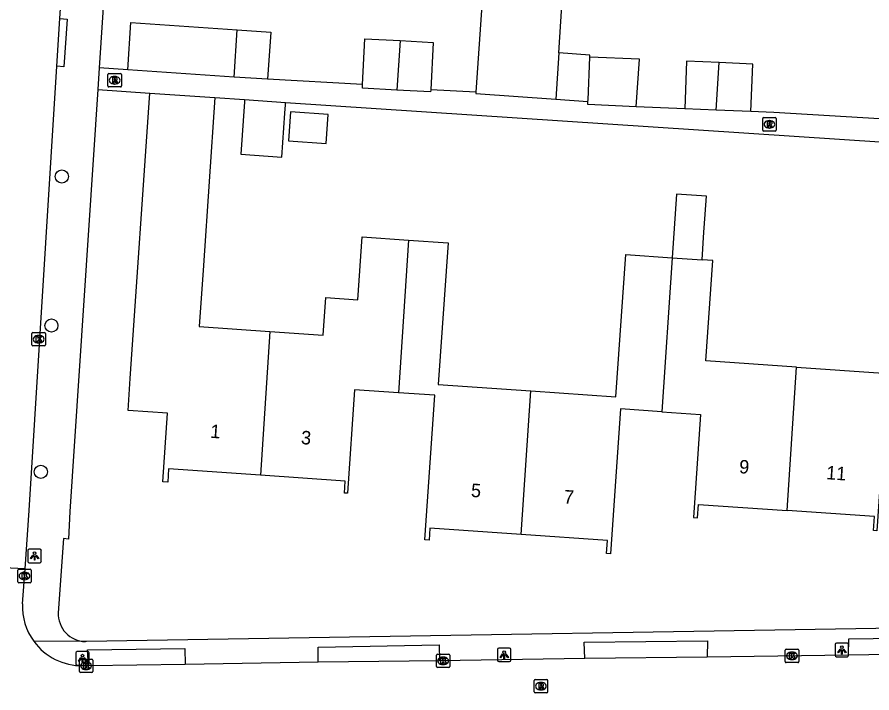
# Model space of a CAD drawing. Extents: x 161848 to 162726, y 385382 to 386521.
# Drawn here: x 162058.5 to 162122, y 385384.8 to 385435 of the extents above; entities that cross this region are included whole.
import ezdxf

# ---------------------------------------------------------------- set-up
doc = ezdxf.new("R2010")
doc.units = 0
for name, color, linetype in [('IMGEO_Boom', 7, 'Continuous'), ('IMGEO_Kolk', 7, 'Continuous'), ('IMGEO_Lichtpunt', 7, 'Continuous'), ('IMGEO_Pand', 7, 'Continuous'), ('IMGEO_Pand_nummerreeks', 7, 'Continuous'), ('IMGEO_Rijbaan_lokaal_open', 7, 'Continuous'), ('IMGEO_Rioolput', 7, 'Continuous'), ('IMGEO_Voetpad_open', 7, 'Continuous')]:
    doc.layers.add(name, color=color, linetype=linetype)

msp = doc.modelspace()

# ---------------------------------------------------------------- linework, layer by layer
at = {"layer": 'IMGEO_Boom'}
for centre in [(162061.81, 385423.185), (162061.04, 385412.111), (162060.257, 385401.24)]:
    msp.add_circle(centre, 0.489, dxfattribs=at)
at = {"layer": 'IMGEO_Kolk'}
for p, q in [((162059.594, 385410.674), (162059.594, 385411.526)), ((162059.669, 385411.6), (162060.521, 385411.6)), ((162060.082, 385411.38), (162060.107, 385411.38)), ((162060.595, 385411.526), (162060.595, 385410.674)), ((162060.521, 385410.6), (162059.669, 385410.6)), ((162060.105, 385410.82), (162060.08, 385410.82)), ((162058.54, 385393.081), (162058.54, 385393.933)), ((162058.615, 385394.007), (162059.467, 385394.007)), ((162059.028, 385393.787), (162059.053, 385393.787)), ((162059.541, 385393.933), (162059.541, 385393.081)), ((162059.467, 385393.007), (162058.615, 385393.007)), ((162059.051, 385393.227), (162059.026, 385393.227)), ((162089.736, 385387.698), (162090.588, 385387.698)), ((162115.596, 385387.142), (162115.596, 385387.994)), ((162115.671, 385388.068), (162116.523, 385388.068)), ((162116.084, 385387.848), (162116.109, 385387.848)), ((162116.597, 385387.994), (162116.597, 385387.142)), ((162063.118, 385386.406), (162063.118, 385387.258)), ((162063.193, 385387.332), (162064.045, 385387.332)), ((162063.606, 385387.112), (162063.631, 385387.112)), ((162064.119, 385387.258), (162064.119, 385386.406)), ((162089.661, 385386.772), (162089.661, 385387.624)), ((162090.149, 385387.478), (162090.174, 385387.478)), ((162090.662, 385387.624), (162090.662, 385386.772)), ((162116.523, 385387.068), (162115.671, 385387.068)), ((162116.107, 385387.288), (162116.082, 385387.288)), ((162063.629, 385386.552), (162063.604, 385386.552)), ((162090.588, 385386.698), (162089.736, 385386.698)), ((162090.172, 385386.918), (162090.147, 385386.918)), ((162064.045, 385386.332), (162063.193, 385386.332))]:
    msp.add_line(p, q, dxfattribs=at)
for points in [[(162059.594, 385410.674), (162059.594, 385411.526)], [(162059.669, 385411.6), (162060.521, 385411.6)], [(162059.915, 385411.3), (162060.038, 385411.3), (162060.038, 385411.149), (162060.168, 385411.3), (162060.332, 385411.3), (162060.186, 385411.149), (162060.339, 385410.9), (162060.187, 385410.9), (162060.102, 385411.064), (162060.038, 385410.997), (162060.038, 385410.9), (162059.915, 385410.9), (162059.915, 385411.3)], [(162060.595, 385411.526), (162060.595, 385410.674)], [(162060.521, 385410.6), (162059.669, 385410.6)], [(162058.54, 385393.081), (162058.54, 385393.933)], [(162058.615, 385394.007), (162059.467, 385394.007)], [(162058.861, 385393.707), (162058.984, 385393.707), (162058.984, 385393.556), (162059.114, 385393.707), (162059.278, 385393.707), (162059.132, 385393.556), (162059.285, 385393.307), (162059.133, 385393.307), (162059.048, 385393.471), (162058.984, 385393.404), (162058.984, 385393.307), (162058.861, 385393.307), (162058.861, 385393.707)], [(162059.541, 385393.933), (162059.541, 385393.081)], [(162059.467, 385393.007), (162058.615, 385393.007)], [(162089.736, 385387.698), (162090.588, 385387.698)], [(162115.596, 385387.142), (162115.596, 385387.994)], [(162115.671, 385388.068), (162116.523, 385388.068)], [(162115.917, 385387.768), (162116.04, 385387.768), (162116.04, 385387.617), (162116.17, 385387.768), (162116.334, 385387.768), (162116.188, 385387.617), (162116.341, 385387.368), (162116.189, 385387.368), (162116.104, 385387.532), (162116.04, 385387.465), (162116.04, 385387.368), (162115.917, 385387.368), (162115.917, 385387.768)], [(162116.597, 385387.994), (162116.597, 385387.142)], [(162063.118, 385386.406), (162063.118, 385387.258)], [(162063.193, 385387.332), (162064.045, 385387.332)], [(162064.119, 385387.258), (162064.119, 385386.406)], [(162089.661, 385386.772), (162089.661, 385387.624)], [(162089.982, 385387.398), (162090.105, 385387.398), (162090.105, 385387.247), (162090.235, 385387.398), (162090.399, 385387.398), (162090.253, 385387.247), (162090.406, 385386.998), (162090.254, 385386.998), (162090.169, 385387.162), (162090.105, 385387.095), (162090.105, 385386.998), (162089.982, 385386.998), (162089.982, 385387.398)], [(162090.662, 385387.624), (162090.662, 385386.772)], [(162116.523, 385387.068), (162115.671, 385387.068)], [(162063.439, 385387.032), (162063.562, 385387.032), (162063.562, 385386.881), (162063.692, 385387.032), (162063.856, 385387.032), (162063.71, 385386.881), (162063.863, 385386.632), (162063.711, 385386.632), (162063.626, 385386.796), (162063.562, 385386.729), (162063.562, 385386.632), (162063.439, 385386.632), (162063.439, 385387.032)], [(162090.588, 385386.698), (162089.736, 385386.698)], [(162064.045, 385386.332), (162063.193, 385386.332)]]:
    msp.add_lwpolyline(points, dxfattribs=at)
for centre, start, end in [((162059.671, 385411.524), 91.55205, 178.44795), ((162059.671, 385411.524), 91.55205, 178.44795), ((162060.519, 385411.524), 1.55205, 88.44795), ((162060.519, 385411.524), 1.55205, 88.44795), ((162059.671, 385410.676), 181.55205, 268.44795), ((162059.671, 385410.676), 181.55205, 268.44795), ((162060.519, 385410.676), 271.55205, 358.44795), ((162060.519, 385410.676), 271.55205, 358.44795), ((162058.617, 385393.931), 91.55205, 178.44795), ((162058.617, 385393.931), 91.55205, 178.44795), ((162059.465, 385393.931), 1.55205, 88.44795), ((162059.465, 385393.931), 1.55205, 88.44795), ((162058.617, 385393.083), 181.55205, 268.44795), ((162058.617, 385393.083), 181.55205, 268.44795), ((162059.465, 385393.083), 271.55205, 358.44795), ((162059.465, 385393.083), 271.55205, 358.44795), ((162089.738, 385387.622), 91.55205, 178.44795), ((162089.738, 385387.622), 91.55205, 178.44795), ((162090.586, 385387.622), 1.55205, 88.44795), ((162090.586, 385387.622), 1.55205, 88.44795), ((162115.673, 385387.992), 91.55205, 178.44795), ((162115.673, 385387.992), 91.55205, 178.44795), ((162116.521, 385387.992), 1.55205, 88.44795), ((162116.521, 385387.992), 1.55205, 88.44795), ((162063.195, 385387.256), 91.55205, 178.44795), ((162063.195, 385387.256), 91.55205, 178.44795), ((162064.043, 385387.256), 1.55205, 88.44795), ((162064.043, 385387.256), 1.55205, 88.44795), ((162115.673, 385387.144), 181.55205, 268.44795), ((162115.673, 385387.144), 181.55205, 268.44795), ((162116.521, 385387.144), 271.55205, 358.44795), ((162116.521, 385387.144), 271.55205, 358.44795), ((162063.195, 385386.408), 181.55205, 268.44795), ((162063.195, 385386.408), 181.55205, 268.44795), ((162064.043, 385386.408), 271.55205, 358.44795), ((162064.043, 385386.408), 271.55205, 358.44795), ((162089.738, 385386.774), 181.55205, 268.44795), ((162089.738, 385386.774), 181.55205, 268.44795), ((162090.586, 385386.774), 271.55205, 358.44795), ((162090.586, 385386.774), 271.55205, 358.44795)]:
    msp.add_arc(centre, 0.0765, start, end, dxfattribs=at)
for centre, major_axis, ratio, start_param, end_param in [((162060.081, 385411.1), (-0.387, 0.002), 0.722429, 4.712389, 7.853982), ((162060.106, 385411.1), (-0.39, 0.002), 0.717154, 1.570796, 4.712389), ((162059.027, 385393.507), (-0.387, 0.002), 0.722429, 4.712389, 7.853982), ((162059.052, 385393.507), (-0.39, 0.002), 0.717154, 1.570796, 4.712389), ((162116.083, 385387.568), (-0.387, 0.002), 0.722429, 4.712389, 7.853982), ((162116.108, 385387.568), (-0.39, 0.002), 0.717154, 1.570796, 4.712389), ((162063.605, 385386.832), (-0.387, 0.002), 0.722429, 4.712389, 7.853982), ((162063.63, 385386.832), (-0.39, 0.002), 0.717154, 1.570796, 4.712389), ((162090.148, 385387.198), (-0.387, 0.002), 0.722429, 4.712389, 7.853982), ((162090.173, 385387.198), (-0.39, 0.002), 0.717154, 1.570796, 4.712389)]:
    msp.add_ellipse(centre, major_axis=major_axis, ratio=ratio, start_param=start_param, end_param=end_param, dxfattribs=at)
at = {"layer": 'IMGEO_Lichtpunt'}
for p, q in [((162059.294, 385395.395), (162059.294, 385394.588)), ((162059.294, 385395.395), (162059.294, 385394.588)), ((162060.196, 385395.49), (162059.388, 385395.49)), ((162060.196, 385395.49), (162059.388, 385395.49)), ((162060.29, 385394.588), (162060.29, 385395.395)), ((162060.29, 385394.588), (162060.29, 385395.395)), ((162059.388, 385394.494), (162060.196, 385394.494)), ((162059.388, 385394.494), (162060.196, 385394.494)), ((162119.313, 385388.411), (162119.313, 385387.604)), ((162119.313, 385388.411), (162119.313, 385387.604)), ((162120.215, 385388.506), (162119.407, 385388.506)), ((162120.215, 385388.506), (162119.407, 385388.506)), ((162120.309, 385387.604), (162120.309, 385388.411)), ((162120.309, 385387.604), (162120.309, 385388.411)), ((162062.858, 385387.788), (162062.858, 385386.981)), ((162062.858, 385387.788), (162062.858, 385386.981)), ((162063.76, 385387.883), (162062.952, 385387.883)), ((162063.76, 385387.883), (162062.952, 385387.883)), ((162063.854, 385386.981), (162063.854, 385387.788)), ((162063.854, 385386.981), (162063.854, 385387.788)), ((162094.205, 385388.053), (162094.205, 385387.246)), ((162094.205, 385388.053), (162094.205, 385387.246)), ((162095.107, 385388.148), (162094.299, 385388.148)), ((162095.107, 385388.148), (162094.299, 385388.148)), ((162095.201, 385387.246), (162095.201, 385388.053)), ((162095.201, 385387.246), (162095.201, 385388.053)), ((162094.299, 385387.152), (162095.107, 385387.152)), ((162094.299, 385387.152), (162095.107, 385387.152)), ((162119.407, 385387.51), (162120.215, 385387.51)), ((162119.407, 385387.51), (162120.215, 385387.51)), ((162062.952, 385386.887), (162063.76, 385386.887)), ((162062.952, 385386.887), (162063.76, 385386.887))]:
    msp.add_line(p, q, dxfattribs=at)
for points in [[(162059.668, 385395.059), (162059.707, 385395.031), (162059.519, 385394.769), (162059.481, 385394.796), (162059.668, 385395.059)], [(162059.77, 385395.011), (162059.817, 385395.011), (162059.817, 385394.689), (162059.77, 385394.689), (162059.77, 385395.011)], [(162059.88, 385395.031), (162059.918, 385395.058), (162060.105, 385394.796), (162060.066, 385394.768), (162059.88, 385395.031)], [(162094.579, 385387.717), (162094.618, 385387.689), (162094.43, 385387.427), (162094.392, 385387.454), (162094.579, 385387.717)], [(162094.791, 385387.689), (162094.829, 385387.716), (162095.016, 385387.454), (162094.977, 385387.426), (162094.791, 385387.689)], [(162119.687, 385388.075), (162119.726, 385388.047), (162119.538, 385387.785), (162119.5, 385387.812), (162119.687, 385388.075)], [(162119.789, 385388.027), (162119.836, 385388.027), (162119.836, 385387.705), (162119.789, 385387.705), (162119.789, 385388.027)], [(162119.899, 385388.047), (162119.937, 385388.074), (162120.124, 385387.812), (162120.085, 385387.784), (162119.899, 385388.047)], [(162063.232, 385387.452), (162063.271, 385387.424), (162063.083, 385387.162), (162063.045, 385387.189), (162063.232, 385387.452)], [(162063.334, 385387.404), (162063.381, 385387.404), (162063.381, 385387.082), (162063.334, 385387.082), (162063.334, 385387.404)], [(162063.444, 385387.424), (162063.482, 385387.451), (162063.669, 385387.189), (162063.63, 385387.161), (162063.444, 385387.424)], [(162094.681, 385387.669), (162094.728, 385387.669), (162094.728, 385387.347), (162094.681, 385387.347), (162094.681, 385387.669)]]:
    msp.add_lwpolyline(points, dxfattribs=at)
for centre in [(162059.793, 385395.193), (162119.812, 385388.209), (162063.357, 385387.586), (162094.704, 385387.851)]:
    msp.add_circle(centre, 0.0994, dxfattribs=at)
for centre, start, end in [((162059.388, 385395.395), 90, 180), ((162059.388, 385395.395), 90, 180), ((162060.196, 385395.395), 0, 90), ((162060.196, 385395.395), 0, 90), ((162059.388, 385394.588), 180, 270), ((162059.388, 385394.588), 180, 270), ((162060.196, 385394.588), 270, 0), ((162060.196, 385394.588), 270, 360), ((162119.407, 385388.411), 90, 180), ((162119.407, 385388.411), 90, 180), ((162120.215, 385388.411), 0, 90), ((162120.215, 385388.411), 0, 90), ((162062.952, 385387.788), 90, 180), ((162062.952, 385387.788), 90, 180), ((162063.76, 385387.788), 0, 90), ((162063.76, 385387.788), 0, 90), ((162094.299, 385388.053), 90, 180), ((162094.299, 385388.053), 90, 180), ((162095.107, 385388.053), 0, 90), ((162095.107, 385388.053), 0, 90), ((162094.299, 385387.246), 180, 270), ((162094.299, 385387.246), 180, 270), ((162095.107, 385387.246), 270, 0), ((162095.107, 385387.246), 270, 360), ((162119.407, 385387.604), 180, 270), ((162119.407, 385387.604), 180, 270), ((162120.215, 385387.604), 270, 0), ((162120.215, 385387.604), 270, 360), ((162062.952, 385386.981), 180, 270), ((162062.952, 385386.981), 180, 270), ((162063.76, 385386.981), 270, 0), ((162063.76, 385386.981), 270, 360)]:
    msp.add_arc(centre, 0.0946, start, end, dxfattribs=at)
at = {"layer": 'IMGEO_Pand'}
for points in [[(162098.76, 385432.364), (162098.983, 385435.878), (162093.075, 385436.25), (162092.603, 385429.445)], [(162066.717, 385431.115), (162066.955, 385434.618), (162074.85, 385434.081)], [(162074.627, 385430.577), (162074.85, 385434.081)], [(162074.85, 385434.081), (162077.351, 385433.911), (162077.113, 385430.408)], [(162084.171, 385430.029), (162084.353, 385433.425), (162086.975, 385433.284)], [(162086.975, 385433.284), (162086.728, 385429.601)], [(162086.975, 385433.284), (162089.428, 385433.152), (162089.239, 385429.626)], [(162098.76, 385432.364), (162098.543, 385428.931)], [(162101.068, 385432.046), (162101.075, 385432.204), (162098.76, 385432.364)], [(162100.931, 385428.766), (162100.936, 385428.887), (162101.068, 385432.046)], [(162104.524, 385428.373), (162104.758, 385431.892), (162101.068, 385432.046)], [(162110.691, 385431.645), (162108.267, 385431.746), (162108.121, 385428.223)], [(162110.457, 385428.126), (162110.691, 385431.645)], [(162113.039, 385428.018), (162113.186, 385431.541), (162110.691, 385431.645)], [(162074.627, 385430.577), (162066.717, 385431.115)], [(162077.113, 385430.408), (162074.627, 385430.577)], [(162086.728, 385429.601), (162084.155, 385429.739), (162084.171, 385430.029)], [(162089.239, 385429.626), (162089.23, 385429.467), (162086.728, 385429.601)], [(162076.587, 385400.988), (162069.755, 385401.461), (162069.688, 385400.487), (162069.323, 385400.512), (162069.675, 385405.591), (162066.735, 385405.795), (162066.901, 385408.189), (162068.369, 385429.385)], [(162068.369, 385429.385), (162073.201, 385429.05)], [(162073.201, 385429.05), (162072.336, 385416.565), (162072.023, 385412.039), (162077.275, 385411.676)], [(162092.603, 385429.445), (162092.596, 385429.344), (162098.543, 385428.931)], [(162075.397, 385428.898), (162075.386, 385428.728), (162075.116, 385424.836), (162078.17, 385424.625), (162078.396, 385427.896), (162078.439, 385428.516), (162078.451, 385428.686)], [(162075.397, 385428.898), (162078.451, 385428.686)], [(162098.543, 385428.931), (162100.931, 385428.766)], [(162104.524, 385428.373), (162100.921, 385428.523), (162100.931, 385428.766)], [(162078.677, 385425.839), (162081.455, 385425.647), (162081.604, 385427.804), (162078.826, 385427.997), (162078.677, 385425.839)], [(162110.457, 385428.126), (162108.121, 385428.223)], [(162113.039, 385428.018), (162110.457, 385428.126)], [(162109.41, 385416.996), (162109.549, 385419.048), (162109.571, 385419.372), (162109.731, 385421.732), (162107.506, 385421.883), (162107.186, 385417.151)], [(162116.44, 385409.024), (162122.868, 385408.579), (162123.595, 385419.07), (162126.955, 385418.837)], [(162077.275, 385411.676), (162081.235, 385411.401), (162081.429, 385414.192), (162083.828, 385414.026), (162084.152, 385418.7), (162087.58, 385418.463)], [(162087.58, 385418.463), (162086.855, 385407.116)], [(162087.58, 385418.463), (162090.525, 385418.259), (162089.795, 385407.73), (162096.68, 385407.253)], [(162096.68, 385407.253), (162103.003, 385406.814), (162103.736, 385417.39), (162107.186, 385417.151)], [(162107.186, 385417.151), (162106.411, 385405.709)], [(162107.186, 385417.151), (162109.41, 385416.996)], [(162116.44, 385409.024), (162109.688, 385409.492), (162110.205, 385416.941), (162109.41, 385416.996)], [(162077.275, 385411.676), (162076.587, 385400.988)], [(162115.731, 385398.372), (162116.44, 385409.024)], [(162126.197, 385407.517), (162123.156, 385407.728), (162122.403, 385396.856), (162122.15, 385396.873), (162122.223, 385397.922), (162115.731, 385398.372)], [(162086.855, 385407.116), (162083.573, 385407.344), (162083.04, 385399.654), (162082.826, 385399.669), (162082.887, 385400.551), (162076.587, 385400.988)], [(162095.969, 385396.598), (162089.183, 385397.068), (162089.12, 385396.158), (162088.793, 385396.181), (162089.537, 385406.93), (162086.855, 385407.116)], [(162095.969, 385396.598), (162096.68, 385407.253)], [(162106.411, 385405.709), (162103.341, 385405.922), (162102.596, 385395.163), (162102.315, 385395.183), (162102.383, 385396.154), (162095.969, 385396.598)], [(162106.411, 385405.709), (162109.294, 385405.509), (162108.763, 385397.846), (162109.08, 385397.824), (162109.15, 385398.828), (162115.731, 385398.372)]]:
    msp.add_lwpolyline(points, dxfattribs=at)
at = {"layer": 'IMGEO_Rijbaan_lokaal_open'}
for points in [[(162061.665, 385434.915), (162063.012, 385455.274)], [(162061.431, 385431.375), (162061.665, 385434.915)], [(162059.079, 385394.035), (162059.396, 385398.383), (162061.431, 385431.375)], [(162059.079, 385394.035), (162052.098, 385394.353)], [(162058.889, 385391.429), (162059.079, 385394.035)], [(162129.374, 385387.774), (162120.31, 385387.623)], [(162080.873, 385387.09), (162070.989, 385386.922)], [(162089.885, 385387.193), (162080.873, 385387.09)], [(162100.697, 385387.385), (162089.885, 385387.193)], [(162109.802, 385387.486), (162100.697, 385387.385)], [(162120.31, 385387.623), (162109.802, 385387.486)], [(162063.795, 385386.826), (162063.367, 385386.841)], [(162070.989, 385386.922), (162063.795, 385386.826)]]:
    msp.add_lwpolyline(points, dxfattribs=at)
for centre, radius, start, end in [((162063.295, 385391.251), 4.41, 177.69135, 216.11934), ((162063.294, 385391.246), 4.406, 216.07208, 270.94928)]:
    msp.add_arc(centre, radius, start, end, dxfattribs=at)
at = {"layer": 'IMGEO_Rioolput'}
for p, q in [((162065.241, 385429.91), (162065.241, 385430.762)), ((162065.316, 385430.836), (162066.168, 385430.836)), ((162065.729, 385430.616), (162065.754, 385430.616)), ((162066.242, 385430.762), (162066.242, 385429.91)), ((162066.168, 385429.836), (162065.316, 385429.836)), ((162065.752, 385430.056), (162065.727, 385430.056)), ((162113.919, 385426.635), (162113.919, 385427.487)), ((162113.994, 385427.561), (162114.846, 385427.561)), ((162114.407, 385427.341), (162114.432, 385427.341)), ((162114.92, 385427.487), (162114.92, 385426.635)), ((162114.846, 385426.561), (162113.994, 385426.561)), ((162114.43, 385426.781), (162114.405, 385426.781)), ((162097.007, 385385.82), (162097.859, 385385.82)), ((162096.932, 385384.894), (162096.932, 385385.746)), ((162097.42, 385385.6), (162097.445, 385385.6)), ((162097.933, 385385.746), (162097.933, 385384.894)), ((162097.859, 385384.82), (162097.007, 385384.82)), ((162097.443, 385385.04), (162097.418, 385385.04))]:
    msp.add_line(p, q, dxfattribs=at)
for points in [[(162065.241, 385429.91), (162065.241, 385430.762)], [(162065.316, 385430.836), (162066.168, 385430.836)], [(162065.83, 385430.534), (162065.578, 385430.536), (162065.578, 385430.136)], [(162065.578, 385430.136), (162065.702, 385430.136), (162065.702, 385430.298), (162065.713, 385430.298)], [(162065.756, 385430.455), (162065.702, 385430.455), (162065.702, 385430.374)], [(162065.702, 385430.374), (162065.754, 385430.374)], [(162065.76, 385430.269), (162065.831, 385430.136), (162065.971, 385430.136), (162065.906, 385430.262)], [(162066.242, 385430.762), (162066.242, 385429.91)], [(162066.168, 385429.836), (162065.316, 385429.836)], [(162113.919, 385426.635), (162113.919, 385427.487)], [(162113.994, 385427.561), (162114.846, 385427.561)], [(162114.508, 385427.259), (162114.256, 385427.261), (162114.256, 385426.861)], [(162114.434, 385427.18), (162114.38, 385427.18), (162114.38, 385427.099)], [(162114.38, 385427.099), (162114.432, 385427.099)], [(162114.92, 385427.487), (162114.92, 385426.635)], [(162114.846, 385426.561), (162113.994, 385426.561)], [(162114.256, 385426.861), (162114.38, 385426.861), (162114.38, 385427.023), (162114.391, 385427.023)], [(162114.438, 385426.994), (162114.509, 385426.861), (162114.649, 385426.861), (162114.584, 385426.987)], [(162097.007, 385385.82), (162097.859, 385385.82)], [(162096.932, 385384.894), (162096.932, 385385.746)], [(162097.521, 385385.518), (162097.269, 385385.52), (162097.269, 385385.12)], [(162097.269, 385385.12), (162097.393, 385385.12), (162097.393, 385385.282), (162097.404, 385385.282)], [(162097.447, 385385.439), (162097.393, 385385.439), (162097.393, 385385.358)], [(162097.393, 385385.358), (162097.445, 385385.358)], [(162097.451, 385385.253), (162097.522, 385385.12), (162097.662, 385385.12), (162097.597, 385385.246)], [(162097.933, 385385.746), (162097.933, 385384.894)], [(162097.859, 385384.82), (162097.007, 385384.82)]]:
    msp.add_lwpolyline(points, dxfattribs=at)
for centre, radius, start, end in [((162065.318, 385430.76), 0.0765, 91.55205, 178.44795), ((162065.318, 385430.76), 0.0765, 91.55205, 178.44795), ((162065.712, 385430.245), 0.0533, 26.02933, 88.69889), ((162065.738, 385430.563), 0.19, 274.7715, 282.96867), ((162065.762, 385430.359), 0.0964, 77.00612, 93.18647), ((162065.776, 385430.416), 0.0378, 276.66336, 79.67722), ((162065.829, 385430.424), 0.109, 350.36119, 89.41601), ((162065.827, 385430.424), 0.112, 277.58423, 350.98172), ((162065.811, 385430.209), 0.108, 29.51342, 73.79051), ((162066.166, 385430.76), 0.0765, 1.55205, 88.44795), ((162066.166, 385430.76), 0.0765, 1.55205, 88.44795), ((162065.318, 385429.912), 0.0765, 181.55205, 268.44795), ((162065.318, 385429.912), 0.0765, 181.55205, 268.44795), ((162066.166, 385429.912), 0.0765, 271.55205, 358.44795), ((162066.166, 385429.912), 0.0765, 271.55205, 358.44795), ((162113.996, 385427.485), 0.0765, 91.55205, 178.44795), ((162113.996, 385427.485), 0.0765, 91.55205, 178.44795), ((162114.416, 385427.288), 0.19, 274.7715, 282.96867), ((162114.44, 385427.084), 0.0964, 77.00612, 93.18647), ((162114.454, 385427.141), 0.0378, 276.66336, 79.67722), ((162114.507, 385427.149), 0.109, 350.36119, 89.41601), ((162114.505, 385427.149), 0.112, 277.58423, 350.98172), ((162114.844, 385427.485), 0.0765, 1.55205, 88.44795), ((162114.844, 385427.485), 0.0765, 1.55205, 88.44795), ((162113.996, 385426.637), 0.0765, 181.55205, 268.44795), ((162113.996, 385426.637), 0.0765, 181.55205, 268.44795), ((162114.39, 385426.97), 0.0533, 26.02933, 88.69889), ((162114.489, 385426.934), 0.108, 29.51342, 73.79051), ((162114.844, 385426.637), 0.0765, 271.55205, 358.44795), ((162114.844, 385426.637), 0.0765, 271.55205, 358.44795), ((162097.009, 385385.744), 0.0765, 91.55205, 178.44795), ((162097.009, 385385.744), 0.0765, 91.55205, 178.44795), ((162097.857, 385385.744), 0.0765, 1.55205, 88.44795), ((162097.857, 385385.744), 0.0765, 1.55205, 88.44795), ((162097.403, 385385.229), 0.0533, 26.02933, 88.69889), ((162097.429, 385385.547), 0.19, 274.7715, 282.96867), ((162097.453, 385385.343), 0.0964, 77.00612, 93.18647), ((162097.467, 385385.4), 0.0378, 276.66336, 79.67722), ((162097.52, 385385.408), 0.109, 350.36119, 89.41601), ((162097.518, 385385.408), 0.112, 277.58423, 350.98172), ((162097.502, 385385.193), 0.108, 29.51342, 73.79051), ((162097.009, 385384.896), 0.0765, 181.55205, 268.44795), ((162097.009, 385384.896), 0.0765, 181.55205, 268.44795), ((162097.857, 385384.896), 0.0765, 271.55205, 358.44795), ((162097.857, 385384.896), 0.0765, 271.55205, 358.44795)]:
    msp.add_arc(centre, radius, start, end, dxfattribs=at)
for centre, major_axis, ratio, start_param, end_param in [((162065.728, 385430.336), (-0.387, 0.002), 0.722429, 4.712389, 7.853982), ((162065.753, 385430.336), (-0.39, 0.002), 0.717154, 1.570796, 4.712389), ((162114.406, 385427.061), (-0.387, 0.002), 0.722429, 4.712389, 7.853982), ((162114.431, 385427.061), (-0.39, 0.002), 0.717154, 1.570796, 4.712389), ((162097.419, 385385.32), (-0.387, 0.002), 0.722429, 4.712389, 7.853982), ((162097.444, 385385.32), (-0.39, 0.002), 0.717154, 1.570796, 4.712389)]:
    msp.add_ellipse(centre, major_axis=major_axis, ratio=ratio, start_param=start_param, end_param=end_param, dxfattribs=at)
at = {"layer": 'IMGEO_Voetpad_open'}
for points in [[(162066.209, 385455.593), (162064.597, 385431.255)], [(162061.665, 385434.915), (162062.206, 385434.878), (162061.963, 385431.339), (162061.431, 385431.375)], [(162064.597, 385431.255), (162064.49, 385429.642)], [(162066.717, 385431.115), (162064.597, 385431.255)], [(162084.171, 385430.029), (162077.113, 385430.408)], [(162064.49, 385429.642), (162062.414, 385398.297), (162062.302, 385396.232), (162061.944, 385396.281), (162061.552, 385390.777)], [(162064.49, 385429.642), (162068.369, 385429.385)], [(162092.603, 385429.445), (162089.239, 385429.626)], [(162073.201, 385429.05), (162075.397, 385428.898)], [(162078.451, 385428.686), (162146.953, 385424.146)], [(162108.121, 385428.223), (162104.524, 385428.373)], [(162125.504, 385427.309), (162114.743, 385427.947), (162113.039, 385428.018)], [(162208.129, 385391.024), (162063.645, 385388.627), (162063.562, 385388.628)], [(162120.31, 385387.623), (162120.322, 385388.848), (162129.374, 385388.972), (162129.374, 385387.774)], [(162063.562, 385388.628), (162059.733, 385388.652)], [(162080.873, 385387.09), (162080.878, 385388.225), (162089.857, 385388.391), (162089.885, 385387.193)], [(162100.697, 385387.385), (162100.651, 385388.586), (162109.82, 385388.696), (162109.802, 385387.486)], [(162063.795, 385386.826), (162063.717, 385388.023), (162070.949, 385388.106), (162070.989, 385386.922)]]:
    msp.add_lwpolyline(points, dxfattribs=at)
msp.add_arc((162063.616, 385390.693), 2.066, 177.67378, 268.49783, dxfattribs=at)

# ---------------------------------------------------------------- texts
at = {"layer": 'IMGEO_Pand_nummerreeks'}
for s, rotation, p in [('1', 356.03513, (162072.832, 385403.774)), ('3', 356.03595, (162079.573, 385403.307)), ('9', 356.03513, (162112.143, 385401.147)), ('11', 356.03556, (162118.619, 385400.698)), ('5', 356.03902, (162092.207, 385399.385)), ('7', 356.03902, (162099.111, 385398.907))]:
    msp.add_text(s, height=1, rotation=rotation, dxfattribs=at).set_placement(p)

doc.saveas('drawing.dxf')
